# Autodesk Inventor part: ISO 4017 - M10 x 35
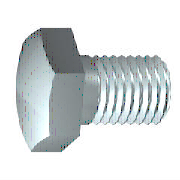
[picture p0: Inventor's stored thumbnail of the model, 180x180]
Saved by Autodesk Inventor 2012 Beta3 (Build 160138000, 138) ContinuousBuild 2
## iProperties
Created: 2010-11
Part Number: ISO 4017 - M10 x 35
Material: Stainless Steel, 440C
Description: Hexagon head screws
Document SubType Name: Modeling
Standard: ISO 4017
Designer: Beta-8540w
Standard Revision: Third edition 1999-08-15
Standards Organization: ISO
Language: en-US
Size Designation: M10 x 35
Categories: <MemberInstance><Categories><Category DisplayName="Fasteners" InternalName="e4da775c-781d-43d5-af7c-5136215cf5a6" Mnemonic="FSTN"><Category DisplayName="Bolts"
Density: 7.75 g/cm^3
IsCustomPart: 0
Author: Beta-8540w
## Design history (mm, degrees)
body "Solid1"
workplane "Work Plane1"
revolve "Body" stored, may be unused: angle "d12" = 90 deg
sketch "Sketch2"
  geometry: L1 (0, 9.238)-(8, 4.619); L2 (8, 4.619)-(8, -4.619); L3 (8, -4.619)-(0, -9.238); L4 (0, -9.238)-(-8, -4.619); L5 (-8, -4.619)-(-8, 4.619); L6 (-8, 4.619)-(0, 9.238); 2 further points
  constraints: 12 end point, 1 coincident, 1 vertical, 11 other
  dimensions: "d11" = 16 distance between parallel lines of L5 L2 (= SW)
extrude "Head" join sketch "Sketch2" distance "d3" = 5.8 (= KOH - SD); taper "d4" = 0 deg
revolve "Chamfer1" stored, may be unused: angle "d21" = 90 deg
feature "Thread" dims "d15" = 30.5 (= GEL), "d16" = 0
chamfer "Chamfer2" distance "d6" = 0.92018 (= -0.5 x SPD + 0.5 x GD); stored, may be unused: second distance "d7" = 0.92028 (computed from GUL), angle "d55" = 45 deg
sketch "Sketch1"
  geometry: L1 (0, 7.315)-(0, 5); L2 (4.5, 5)-(35, 5); L3 (35, 5)-(35, 0); L4 (35, 0)-(-0.6, 0); L5 (-7.72, 0)-(42.12, 0) reference; L6 (-0.6, 0)-(-0.6, 7.315); L7 (-0.6, 7.315)-(0, 7.315); L8 (4.5, 5)-(3.58, 5); L9 (3.58, 5)-(0, 5); L10 (0, -1.463)-(0, 8.778) reference
  constraints: 16 end point, 2 collinear, 2 perpendicular, 1 parallel
  dimensions: "d0" = 35 distance between parallel lines of L3 L1 (= NLG); "d1" = 30.5 distance from line of L2.start L3 (= GEL); "d2" = 10 diameter of L2 L4 (= GD); "d9" = 0.6001 distance between parallel lines of L6 L1 (computed from SD); "d10" = 14.63 diameter of L7 L4 (= SD2); "d13" = 0.92028 distance of L2.start L8.end (computed from GAL); "d14" = 10 diameter of L9 L4 (= BDM)
sketch "Sketch4"
  geometry: L1 (-6.4, 8)-(-6.4, 9.238); L2 (-6.4, 9.238)-(-5.686, 9.238); L3 (-5.686, 9.238)-(-6.4, 8); L4 (-7.56, 0)-(0.56, 0) reference; L5 (-0.6, 9.238)-(-6.4, 9.238) reference; L6 (-6.4, 4.619)-(-6.4, 9.238) reference
  constraints: 6 end point, 2 collinear, 1 perpendicular, 1 vertical
  dimensions: "d5" = 30 deg angle of L3 L1 (= ANG1); "d19" = 16 diameter of L1.start L4 (= SW0)
other parameters: "NLG" = 35 [user parameter; used in 1 equation term], "GD" = 10 (= NND) [user parameter; used in 2 equation terms], "BDM" = 10 (= NND) [user parameter; used in 1 equation term], "KOH" = 6.4 [user parameter; used in 1 equation term], "GEL" = 30.5 [user parameter; used in 2 equation terms], "SW" = 16 [user parameter; used in 2 equation terms], "SW0" = 16 (= SW) [user parameter; used in 1 equation term], "SPD" = 8.15965 (= NND - 1.2269 x PTC) [user parameter; used in 1 equation term], "SD2" = 14.63 [user parameter; used in 2 equation terms], "SD" = 0.6 [user parameter; used in 2 equation terms], "ANG1" = 30 deg [user parameter; used in 1 equation term], "GAL" = 0.92018 (= 0.61345 x PTC) [user parameter; used in 1 equation term], "GUL" = 0.92018 (= 0.61345 x PTC) [user parameter; used in 1 equation term], "d8" = 0, "RR" = 0.4 [user parameter], "d57" = 0, "d58" = 0, "TPU" = 6.66667 (computed from PTC) [user parameter], "GD1" = 8.15965 (= THREADDIA - 1.2269 x PTC) [user parameter], "SDH" = 14.63 (= SD2) [user parameter], "SDHG" = 4.5 [user parameter], "TOA" = 30 deg [user parameter], "PTC" = 1.5 [user parameter; used in 5 equation terms], "E0" = 18.48 [user parameter]
